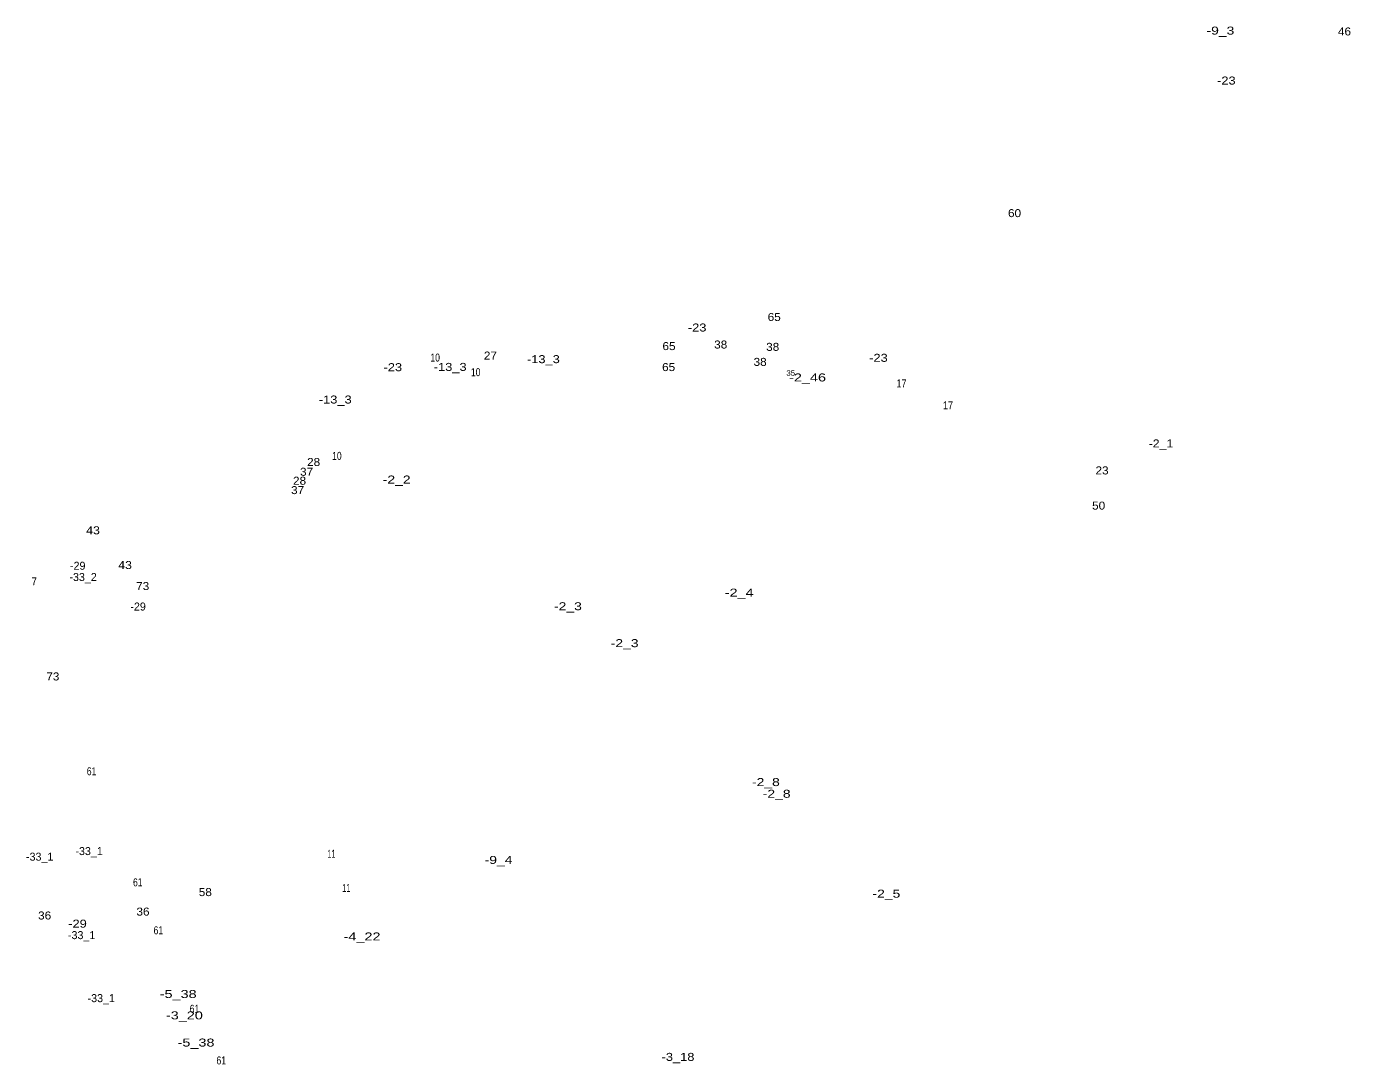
# Model space of a CAD drawing. Extents: x -660778 to -658007, y -986975 to -985382.
# Drawn here: x -658669 to -658007, y -985901 to -985382 of the extents above; entities that cross this region are included whole.
import ezdxf
from ezdxf.enums import TextEntityAlignment as Align

# ---------------------------------------------------------------- set-up
doc = ezdxf.new("R2010")
doc.units = 0
doc.header["$LTSCALE"] = 1.6
doc.layers.add('24', color=7, linetype='Continuous')

msp = doc.modelspace()

# ---------------------------------------------------------------- texts
at = {"layer": '24'}
for s, height, width, p in [('-9_3', 4, 1.3, (-658072.32, -985385.75)), ('46', 4, 1.1, (-658010.3, -985386.18)), ('-23', 4, 1.2, (-658069.35, -985410.73)), ('60', 4, 1.1, (-658175.231, -985477.02)), ('65', 4, 1.1, (-658295.35, -985528.95)), ('-23', 4, 1.2, (-658333.87, -985534.22)), ('65', 4, 1.1, (-658347.95, -985543.51)), ('38', 4, 1.1, (-658322.1, -985542.72)), ('38', 4, 1.1, (-658296.11, -985543.89)), ('10', 4, 0.8, (-658464.83, -985549.24)), ('27', 4, 1.1, (-658437.22, -985548.23)), ('-13_3', 4, 1.2, (-658410.73, -985550.04)), ('38', 4, 1.1, (-658302.4, -985551.4)), ('-23', 4, 1.2, (-658243.26, -985549.37)), ('-23', 4, 1.2, (-658486, -985554.05)), ('-13_3', 4, 1.2, (-658457.319, -985553.92)), ('10', 4, 0.8, (-658444.57, -985556.55)), ('65', 4, 1.1, (-658348.14, -985554)), ('35', 2.68, 1.1, (-658287.09, -985556.3)), ('-2_46', 4, 1.35, (-658278.7, -985559.19)), ('17', 4, 0.85, (-658231.74, -985562.15)), ('-13_3', 4, 1.2, (-658514.77, -985570.23)), ('17', 4, 0.85, (-658208.481, -985573.12)), ('-2_1', 4, 1.15, (-658102.049, -985592.2)), ('28', 4, 1.1, (-658525.59, -985601.46)), ('10', 4, 0.8, (-658513.96, -985598.4)), ('28', 4, 1.1, (-658532.61, -985610.83)), ('37', 4, 1.1, (-658529.1, -985606.34)), ('-2_2', 4, 1.3, (-658484.069, -985610.23)), ('23', 4, 1.1, (-658131.48, -985605.67)), ('37', 4, 1.1, (-658533.59, -985615.51)), ('50', 4, 1.1, (-658133.189, -985623.27)), ('43', 4, 1.15, (-658635.84, -985635.62)), ('43', 4, 1.15, (-658619.84, -985652.98)), ('7', 4, 0.9, (-658665.25, -985661.16)), ('73', 4, 1.1, (-658611.03, -985663.49)), ('-2_4', 4, 1.35, (-658312.87, -985666.8)), ('-2_3', 4, 1.3, (-658398.47, -985673.59)), ('-2_3', 4, 1.3, (-658370.13, -985692.04)), ('73', 4, 1.1, (-658655.95, -985708.69)), ('61', 4, 0.8, (-658636.581, -985756.1)), ('-2_8', 4, 1.3, (-658299.52, -985761.51)), ('-2_8', 4, 1.3, (-658294.14, -985767.34)), ('11', 4, 0.55, (-658516.69, -985797.35)), ('-9_4', 4, 1.3, (-658433.16, -985800.45)), ('61', 4, 0.8, (-658613.481, -985811.63)), ('58', 4, 1.1, (-658579.73, -985816.52)), ('11', 4, 0.55, (-658509.24, -985814.43)), ('-2_5', 4, 1.3, (-658239.29, -985817.31)), ('36', 4, 1.1, (-658660.03, -985828.22)), ('36', 4, 1.1, (-658610.88, -985826.27)), ('-29', 4, 1.2, (-658643.61, -985832.31)), ('61', 4, 0.8, (-658603.201, -985835.63)), ('-4_22', 4, 1.35, (-658501.39, -985838.71)), ('-5_38', 4, 1.35, (-658593.299, -985867.48)), ('61', 4, 0.8, (-658585.15, -985874.85)), ('-3_20', 4, 1.35, (-658590.189, -985878.16)), ('-5_38', 4, 1.35, (-658584.37, -985891.75)), ('61', 4, 0.8, (-658571.75, -985900.68)), ('-3_18', 4, 1.2, (-658343.449, -985898.92))]:
    msp.add_text(s, height=height, dxfattribs=dict(at, width=width)).set_placement(p, align=Align.CENTER)
for s, p in [('-29', (-658643.51, -985653.34)), ('-33_2', (-658640.812, -985658.97)), ('-29', (-658613.32, -985673.73)), ('-33_1', (-658637.816, -985796.01)), ('-33_1', (-658662.516, -985798.81)), ('-33_1', (-658641.546, -985838.03)), ('-33_1', (-658631.746, -985869.54))]:
    msp.add_text(s, height=4, dxfattribs=at).set_placement(p, align=Align.CENTER)

doc.saveas('drawing.dxf')
